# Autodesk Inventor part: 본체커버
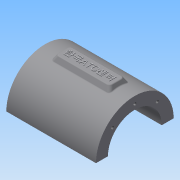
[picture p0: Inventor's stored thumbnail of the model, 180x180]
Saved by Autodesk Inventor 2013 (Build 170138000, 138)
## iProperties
Created: 2015-12
Part Number: 본체커버
Material: 알루미늄 6061
Document SubType Name: Modeling
Designer: mduedu
Density: 2.71 g/cm^3
Mass: 180.742 g
Surface Area: 170.117 cm^2
Volume: 66.6945 cm^3
Author: mduedu
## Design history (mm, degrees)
sketch "스케치1"
  geometry: L1 (45, 40)-(-45, 40); L2 (-45, 40)-(-45, -40); L3 (-45, -40)-(45, -40); L4 (45, -40)-(45, 40); L5 (45, 40)-(-45, -40); L6 (-45, 40)-(45, -40); 1 further point
  constraints: 12 end point, 2 midpoint, 2 parallel, 1 horizontal, 1 perpendicular
  dimensions: "d0" = 90 distance of L2.end L3.end; "d2" = 80 distance of L1.end L2.end
extrude "돌출1" new body sketch "스케치1" distance "d3" = 10; taper "d4" = 0 deg
sketch "스케치2"
  geometry: L1 (0, 40)-(0, -40) reference; C1 r 32.5 at (80, 0); 1 further point
  constraints: 1 centre point
  dimensions: "d5" = 65 diameter of C1; "d6" = 80 distance from line of C1.centre L1
extrude "돌출2" join sketch "스케치2" stored distance "d7" = 75; taper "d8" = 0 deg
sketch "스케치3"
  geometry: L1 (-27.5, -20)-(27.5, -20); L2 (27.5, -20)-(27.5, 20); L3 (27.5, 20)-(-27.5, 20); L4 (-27.5, 20)-(-27.5, -20); L5 (-27.5, -20)-(27.5, 20); L6 (27.5, -20)-(-27.5, 20); 1 further point
  constraints: 12 end point, 2 midpoint, 2 parallel, 1 horizontal, 1 perpendicular
  dimensions: "d9" = 55 distance of L2.end L3.end; "d11" = 40 distance of L1.end L2.end
extrude "돌출3" new body sketch "스케치3" stored distance "d12" = 75; taper "d13" = 0 deg
fillet "모깎기1"
fillet "모깎기2"
feature "결합1"
  node "솔리드2"
fillet "모깎기3" dims "d14" = 10
sketch "스케치4"
  geometry: L1 (-37.5, 47.5)-(37.5, 47.5) reference; L2 (35, 10)-(45, 10) reference; L3 (32.5, 47.5)-(40, 10); L4 (37.5, 47.5)-(37.5, 112.5) reference; L5 (45, 10)-(45, 0) reference; 1 further point
  constraints: 2 end point, 1 midpoint, 1 point on line
  dimensions: "d15" = 5 distance from line of L3.start L4; "d16" = 5 distance from line of L3.end L5
sketch "스케치5"
  geometry: L1 (10, 40)-(10, 30) reference; L2 (10, 35)-(56.569, 22.522); L3 (0, 40)-(10, 40) reference; 2 further points
  constraints: 2 end point, 1 midpoint, 2 other
  dimensions: "d17" = 5 distance from line of L2.start L3; "d18" = 15 deg angle of L2 L3
feature "리브1" dims "d19" = 1, "d20" = 6, "d21" = 0, "d22" = 0, "d23" = 1, "d24" = 1
feature "리브2" dims "d25" = 1, "d26" = 6, "d27" = 0, "d28" = 0, "d29" = 1, "d30" = 1
fillet "모깎기4" dims "d31" = 2
fillet "모깎기5" dims "d32" = 2
fillet "모깎기6" dims "d33" = 2
sketch "스케치6"
  geometry: A1 r 10 centre (-35, 30) between (-35, 40) and (-45, 30) reference; A2 r 10 centre (35, 30) between (45, 30) and (35, 40) reference; A3 r 10 centre (35, -30) between (35, -40) and (45, -30) reference; A4 r 10 centre (-35, -30) between (-45, -30) and (-35, -40) reference; 5 further points
  constraints: 4 coincident
hole "구멍1" sketch "스케치6" at (-35, 30), (35, 30), (35, -30), (-35, -30) diameter "d34" = 7; stored, may be unused: countersink angle "d38" = 90 deg, drill point angle "d40" = 118 deg; dims "d35" = 6, "d36" = 12, "d37" = 3, "d39" = 8
fillet "모깎기7" dims "d41" = 2
hole "구멍2" diameter "d44" = 45; stored, may be unused: countersink angle "d48" = 90 deg, drill point angle "d50" = 118 deg; dims "d42" = 10, "d43" = 10, "d45" = 6, "d46" = 4, "d47" = 2, "d49" = 8
sketch "스케치7" dims "d52" = 26.5
  geometry: L1 (0, 0)-(32.5, 0); L2 (0, 0)-(0, 32.5); A1 r 32.5 centre (0, 0) between (32.5, 0) and (0, 32.5) reference; 3 further points
  constraints: 4 end point, 2 point on circle, 1 coincident, 1 horizontal, 1 point on line, 1 vertical alignment, 2 other
  dimensions: "d51" = 90 deg angle of L2 L1
hole "구멍3" sketch "스케치7" at (0, 26.5) diameter "d54" = 2.459; stored, may be unused: countersink angle "d58" = 90 deg, drill point angle "d60" = 118 deg; dims "d55" = 8, "d56" = 4, "d57" = 2, "d59" = 10
sketch "스케치13"
  geometry: L1 (-45, 80)-(105, 80); L2 (105, 80)-(105, -30); L3 (105, -30)-(-45, -30); L4 (-45, -30)-(-45, 80); L5 (0, 0)-(60, 0) reference; C1 r 32.5 at (30, 80) reference; 1 further point
  constraints: 8 end point, 2 parallel, 1 coincident, 1 horizontal, 1 midpoint, 1 perpendicular
  dimensions: "d99" = 30 distance between parallel lines of L3 L5; "d126" = 150 distance between parallel lines of L2 L4
extrude "돌출8" cut sketch "스케치13" stored distance "d97" = 10; taper "d98" = 0 deg; stored distance "d138" = 10; dims "d2" = 80, "d141" = 1
node "작업 평면4"
  node "작업 평면3"
sketch "스케치19"
  geometry: L1 (-22.5, -6)-(22.5, -6); L2 (22.5, -6)-(22.5, 6); L3 (22.5, 6)-(-22.5, 6); L4 (-22.5, 6)-(-22.5, -6); L5 (-22.5, -6)-(22.5, 6); L6 (22.5, -6)-(-22.5, 6); L7 (-37.5, 32.5)-(-37.5, -32.5) reference; 1 further point
  constraints: 12 end point, 2 midpoint, 2 parallel, 1 horizontal, 1 perpendicular
  dimensions: "d136" = 15 distance between parallel lines of L4 L7; "d137" = 12 distance of L1.end L2.end
extrude "돌출10" join sketch "스케치19" stored distance "d138" = 10; taper "d139" = 30 deg
fillet "모깎기13" dims "d140" = 3
fillet "모깎기14" dims "d141" = 1
fillet "모깎기15" dims "d142" = 1
sketch "스케치20"
  geometry: 2 further points
  constraints: 1 coincident, 1 other
feature "엠보싱2" sketch "스케치20" dims "d0" = 90, "d2" = 80, "d143" = 0.5, "d144" = 0
node "솔리드1"
mirror "대칭1"
mirror "대칭2"
pattern_circular "원형 패턴1" dims angle "d62" = 360 deg
mirror "대칭3"
other parameters: "d135" = 3
